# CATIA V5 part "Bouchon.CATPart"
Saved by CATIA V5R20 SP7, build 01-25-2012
Part number: Bouchon
Bounding box of the stored display mesh (mm): x -7.5 to 7.5, y 0 to 9, z -7.312 to 7.312
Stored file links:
  F:\Travaux\Modélisations\CFAO_2011\MMS\MMS_GR1\AA_OK\bmadec\Catia\Bouchon.CATPart
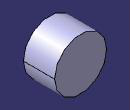
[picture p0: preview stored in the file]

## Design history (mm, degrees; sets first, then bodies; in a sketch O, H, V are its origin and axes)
Body1 (main body)
  Sketch1 on zx-plane, origin (0, 0, 0), H (-1, 0, 0), V (0, 0, 1)
    circle A1 centre (0, 0) radius 7.5
    radius A1 = 7.5
  Pad1: profile Sketch1, direction (0, 1, 0), length 9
